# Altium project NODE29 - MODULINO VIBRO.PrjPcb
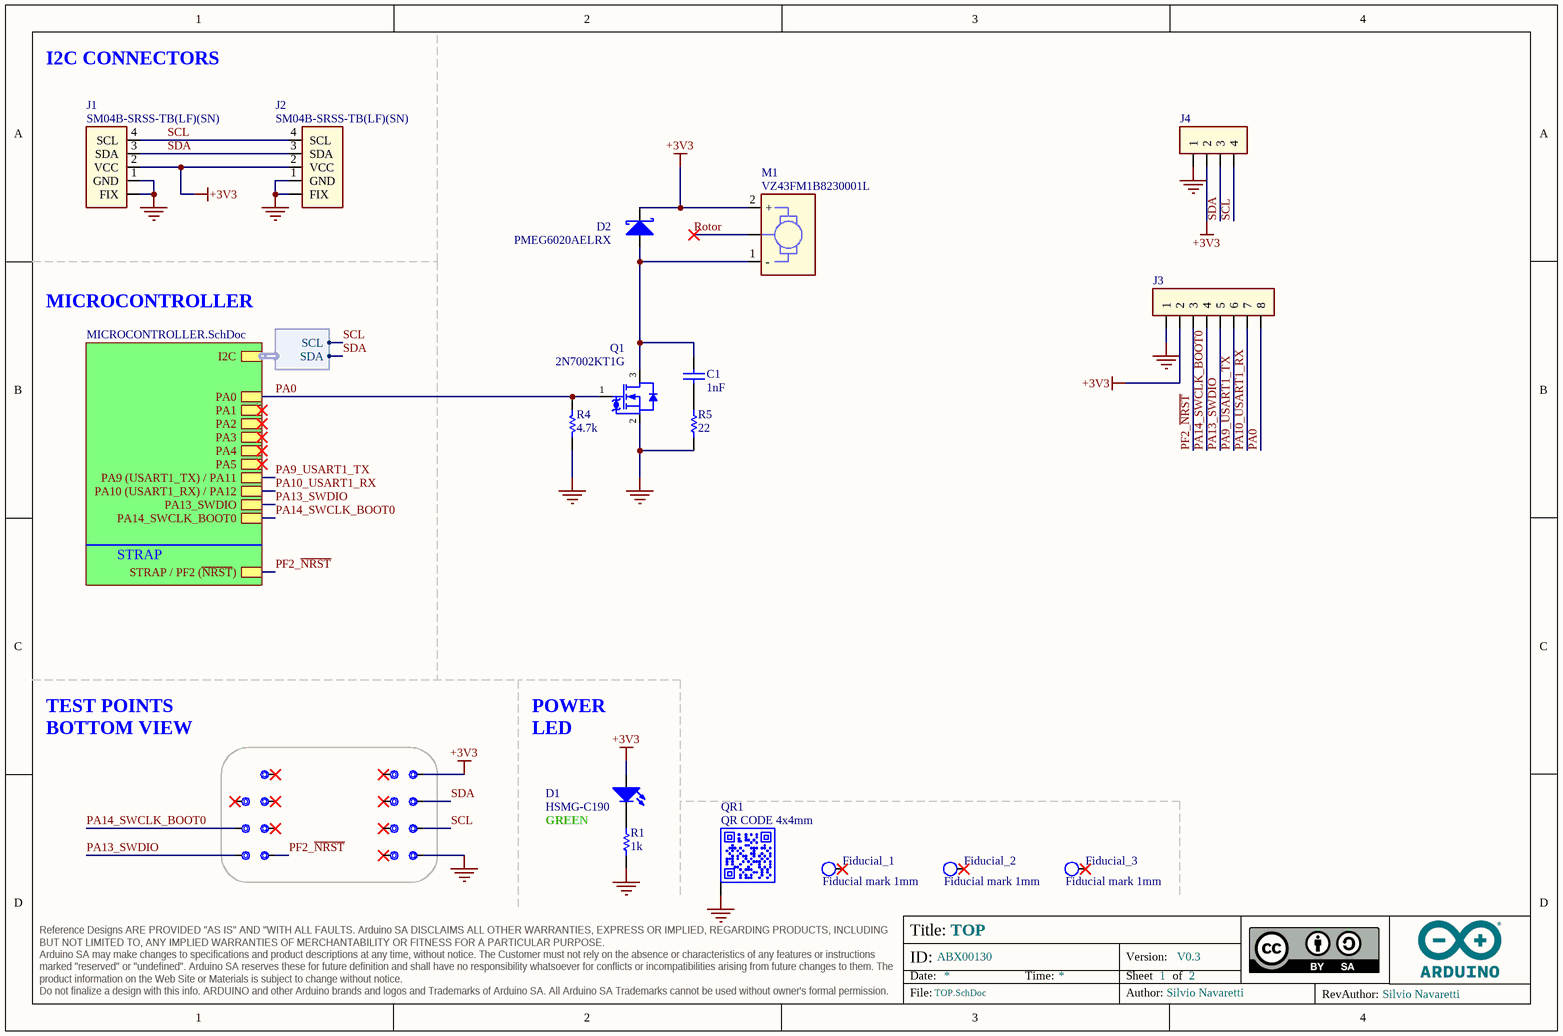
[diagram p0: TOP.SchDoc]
ASSEMBLY_BGA: _; ASSEMBLY_PRESSFIT: _; ASSEMBLY_SMD: X; ASSEMBLY_THT: _; BOARD_CODENAME: NODE29 - MODULINO VIBRO; BOARD_INFO_AUTHOR: Silvio Navaretti; BOARD_INFO_AUTHOR_REV: Silvio Navaretti; BOARD_INFO_Er: _; BOARD_INFO_FLEX: _; BOARD_INFO_FR4: X; BOARD_INFO_FR4_HTG: _; BOARD_INFO_IPC1: _; BOARD_INFO_IPC2: X; BOARD_INFO_IPC3: _; BOARD_INFO_IPC_NA: _; BOARD_INFO_NUMBER_OF_LAYERS: 2; BOARD_INFO_PCB_SIZE: 41.00x25.36mm; BOARD_INFO_POLYMIDE: _; BOARD_INFO_RIGID: X; BOARD_INFO_RIGID/FLEX: _; BOARD_INFO_TBD: _; BOARD_INFO_THICKNESS: 1.6mm; DRILLS_BLIND: _; DRILLS_BURIED: _; DRILLS_COPPER_FILLING: _; DRILLS_FULL: X; DRILLS_LASER: _; DRILLS_PRESSFIT: _; DRILLS_RESIN_FILLING: _; DRILLS_SLOT: _; DRILLS_SOLDER_FILLING: X; FINISH_ADJUSTMENTS: _; FINISH_EDGE_PLATING: _; FINISH_ENIG: _; FINISH_HAL: _; FINISH_HAL_LF: X; FINISH_NI/AU: _; FINISH_SILK_BOTTOM: X; FINISH_SILK_COLOR: WHITE; FINISH_SILK_TOP: X; FINISH_SN/PB: _; FINISH_SOLDERMASK_BOTTOM: X; FINISH_SOLDERMASK_COLOR: BLUE; FINISH_SOLDERMASK_PEELABLE_BOTTOM: _; FINISH_SOLDERMASK_PEELABLE_COLOR: _; FINISH_SOLDERMASK_PEELABLE_TOP: _; FINISH_SOLDERMASK_TOP: X; FINISH_TABS: _; FINISH_TBD: _; INSULATION_MIN_INNER: 0.15mm; INSULATION_MIN_OUTER: 0.15mm; PANEL_MILLING: X; PANEL_NOT_REQUESTED: _; PANEL_NUMBER_OF_FIGURES: 30; PANEL_PROVIDED: X; PANEL_REQUESTED: _; PANEL_SCORING: X; PANEL_SIZE: 262.00x221.00mm; PANEL_TABS: _; SKU: ABX00130; TRACK_MIN_WIDTH_INNER: 0.15mm; TRACK_MIN_WIDTH_OUTER: 0.15mm; Version: V0.3; VIA_1: _; VIA_1_HOLE_MM: _; VIA_1_PAD_MM: _; VIA_2: _; VIA_2_HOLE_MM: _; VIA_2_PAD_MM: _; VIA_3: _; VIA_3_HOLE_MM: _; VIA_3_PAD_MM: _; VIA_4: _; VIA_4_HOLE_MM: _; VIA_4_PAD_MM: _; VIA_5: _; VIA_5_HOLE_MM: _; VIA_5_PAD_MM: _; VIA_THROUGH: X; VIA_THROUGH_HOLE_MM: 0.3; VIA_THROUGH_PAD_MM: 0.6
2 sheets, 42 parts. Net scope: hierarchical (ports join the sheet entries above them; power ports are global).
Board files: PCB.PcbDoc, PANEL.PcbDoc
Sheets:
  TOP.SchDoc
    U_MICROCONTROLLER = MICROCONTROLLER.SchDoc

## Sheet TOP.SchDoc: TOP
size A4; Revision: V0.3; SheetNumber: 1; SheetTotal: 2

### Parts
3V3  Test point 1.00mm  [TP-1.00MM]  (value not drawn)  (no BOM)
C1  value 1nF  [CAP-0402]  (hidden comment: GRM155R71H102KA01D)
D1  HSMG-C190  [LEDC1608X80N-AK]
D2  PMEG6020AELRX  [SOD123-1]
Fiducial_1  Fiducial mark 1mm  [Fiducial mark 1mm-Footprint-1]  (no BOM)
Fiducial_2  Fiducial mark 1mm  [Fiducial mark 1mm-Footprint-1]  (no BOM)
Fiducial_3  Fiducial mark 1mm  [Fiducial mark 1mm-Footprint-1]  (no BOM)
GND  Test point 1.00mm  [TP-1.00MM]  (value not drawn)  (no BOM)
J1  SM04B-SRSS-TB(LF)(SN)  [SM04B-SRSS-TB(LF)(SN)-Footprint-1]
J2  SM04B-SRSS-TB(LF)(SN)  [SM04B-SRSS-TB(LF)(SN)-Footprint-1]
J3  HEADER TH 2.54mm VERT. 1x008POS  [PIN HEADER 2.54mm VERT. 1x8POS]  (value not drawn)  (no BOM)
J4  HEADER TH 2.54mm VERT. 1x004POS  [PIN HEADER 2.54mm VERT. 1x4POS-Footprint-1]  (value not drawn)  (no BOM)
M1  VZ43FM1B8230001L  [VZ43FM1B8230001L]
NRST  Test point 1.00mm  [TP-1.00MM]  (value not drawn)  (no BOM)
PA6  Test point 1.00mm  [TP-1.00MM]  (value not drawn)  (no BOM)
PA7  Test point 1.00mm  [TP-1.00MM]  (value not drawn)  (no BOM)
PC14  Test point 1.00mm  [TP-1.00MM]  (value not drawn)  (no BOM)
PC15  Test point 1.00mm  [TP-1.00MM]  (value not drawn)  (no BOM)
Q1  2N7002KT1G  [SOT23]
QR1  QR CODE 4x4mm  [QR CODE 4x4mm]  (no BOM)
R1  value 1k  [RES-0402]  (hidden comment: CRCW04021K00FKEDC)
R4  value 4.7k  [RES-0402]  (hidden comment: RC0402FR-074K7L)
R5  value 22  [RES-0603]  (hidden comment: CRCW060322R0FKEAC)
SCL  Test point 1.00mm  [TP-1.00MM]  (value not drawn)  (no BOM)
SDA  Test point 1.00mm  [TP-1.00MM]  (value not drawn)  (no BOM)
SWCLK  Test point 1.00mm  [TP-1.00MM]  (value not drawn)  (no BOM)
SWDIO  Test point 1.00mm  [TP-1.00MM]  (value not drawn)  (no BOM)
TP9  Test point 1.00mm  [TP-1.00MM]  (value not drawn)  (no BOM)
TP10  Test point 1.00mm  [TP-1.00MM]  (value not drawn)  (no BOM)
TP11  Test point 1.00mm  [TP-1.00MM]  (value not drawn)  (no BOM)
TP12  Test point 1.00mm  [TP-1.00MM]  (value not drawn)  (no BOM)

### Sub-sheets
U_MICROCONTROLLER = MICROCONTROLLER.SchDoc: I2C (harness I2C), PA0, PA1, PA2, PA3, PA4, PA5, PA13_SWDIO, PA14_SWCLK_BOOT0, PA9 (USART1_TX) / PA11, PA10 (USART1_RX) / PA12, STRAP / PF2 (~{NRST})

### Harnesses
I2C: SDA, SCL

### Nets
+3V3: 3V3.X D1.A D2.C J1.2(VCC) J2.2(VCC) J3.2 J4.2 M1.2(+)
GND: GND.X J1.1(GND) J1.FIX J2.1(GND) J2.FIX J3.1 J4.1 Q1.2(S) QR1.PAD R1.1 R4.2 R5.2
PA0: J3.8 Q1.1(G) R4.1 ; sheet U_MICROCONTROLLER/PA0
PA9_USART1_TX: J3.6 ; sheet U_MICROCONTROLLER/PA9 (USART1_TX) / PA11
PA10_USART1_RX: J3.7 ; sheet U_MICROCONTROLLER/PA10 (USART1_RX) / PA12
PA13_SWDIO: J3.5 SWCLK.X ; sheet U_MICROCONTROLLER/PA13_SWDIO
PA14_SWCLK_BOOT0: J3.4 SWDIO.X ; sheet U_MICROCONTROLLER/PA14_SWCLK_BOOT0
PF2_~{NRST}: J3.3 NRST.X ; sheet U_MICROCONTROLLER/STRAP / PF2 (~{NRST})
Rotor: M1.3  [project net Rotor_1]
SCL: J1.4(SCL) J2.4(SCL) J4.4 SCL.X ; sheet U_MICROCONTROLLER/I2C.SCL
SDA: J1.3(SDA) J2.3(SDA) J4.3 SDA.X ; sheet U_MICROCONTROLLER/I2C.SDA
NetC1_1: C1.1 R5.1
NetC1_2: C1.2 D2.A M1.1(-) Q1.3(D)
NetD1_C: D1.C R1.2

Not connected (* = marked no-connect by the designer): Fiducial_1 1*; Fiducial_2 1*; Fiducial_3 1*; PA6 X*; PA7 X*; PC14 X*; PC15 X*; TP9 X*; TP10 X*; TP11 X*; TP12 X*

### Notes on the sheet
- I2C CONNECTORS
- MICROCONTROLLER
- STRAP
- TEST POINTS BOTTOM VIEW
- (near D1) POWER LED
- GREEN

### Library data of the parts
3V3 GND NRST PA6 PA7 PC14 PC15 SCL SDA SWCLK SWDIO TP9-TP12 = UT0013-A.6: Manufacturer: This is not a component
C1 = C0007-A.15: CAP CHIP 0402 1nF 10% 50V X7R; Manufacturer: KEMET; Code Arduino: 2321
D1 = L0009-A.5: LED SMD 0603 GREEN/568 15mcd 120^; Manufacturer: Broadcom; Code Arduino: 2204
D2 = D0026-A.6: DIODE SCHOTTKY SMD 2A 60V SOD123FL; Manufacturer: Nexperia; Manucturer Part Number 2: SS26L; Code Arduino: 2208; Forward Voltage: 0.6V; Manucturer 2: Hottech
Fiducial_1-Fiducial_3 = UT0023-A.7: Fiducial mark 1mm clearance 2mm
J1 J2 = J0005-A.2: CONN JST 4POS SIDE 1MM TIN QWIIC; Code Arduino: J0005
J3 = J0171-A.4: Code Arduino: J0171
J4 = J0162-A.6: Code Arduino: J0162
M1 = S0061-A.3: MOTOR vibrator, 2.3V to 3.2V, max 75mA, 14000 RPM, DO NOT WASH, heigth 3.4mm, overall length 11mm; Manufacturer: Vybronics Inc; Code Arduino: S0061
Q1 = T0004-A.10: MOSFET N-CH 60V 300mA ESD prot. SOT23; Manufacturer: On Semiconductor; Device Type: Mosfet N-CH SMD; Code Arduino: A5393
QR1 = QR-0001-A.5: QR CODE 4x4mm on layer 34 (This is not a component); Code Arduino: QRCODE_4x4mm
R1 = R0007-A.24: RES CHIP 0402 1k 1% 1/16W; Manufacturer: Vishay; Code Arduino: 0140; Power: 62.5mW; Temperature coefficient: 100ppm
R4 = R0013-A.24: RES CHIP 0402 4k7 1% 1/16W; Manufacturer: YAGEO; Power: 62.5mW; Code Arduino: 2196; Temperature coefficient: 200ppm
R5 = R0121-A.22: RES CHIP 0603 22R 1% 1/10W; Manufacturer: Vishay; Code Arduino: A5106; Temperature coefficient: 100ppm; Power: 100mW

## Sheet MICROCONTROLLER.SchDoc: MICROCONTROLLER
size A4; SheetNumber: 2; SheetTotal: 2
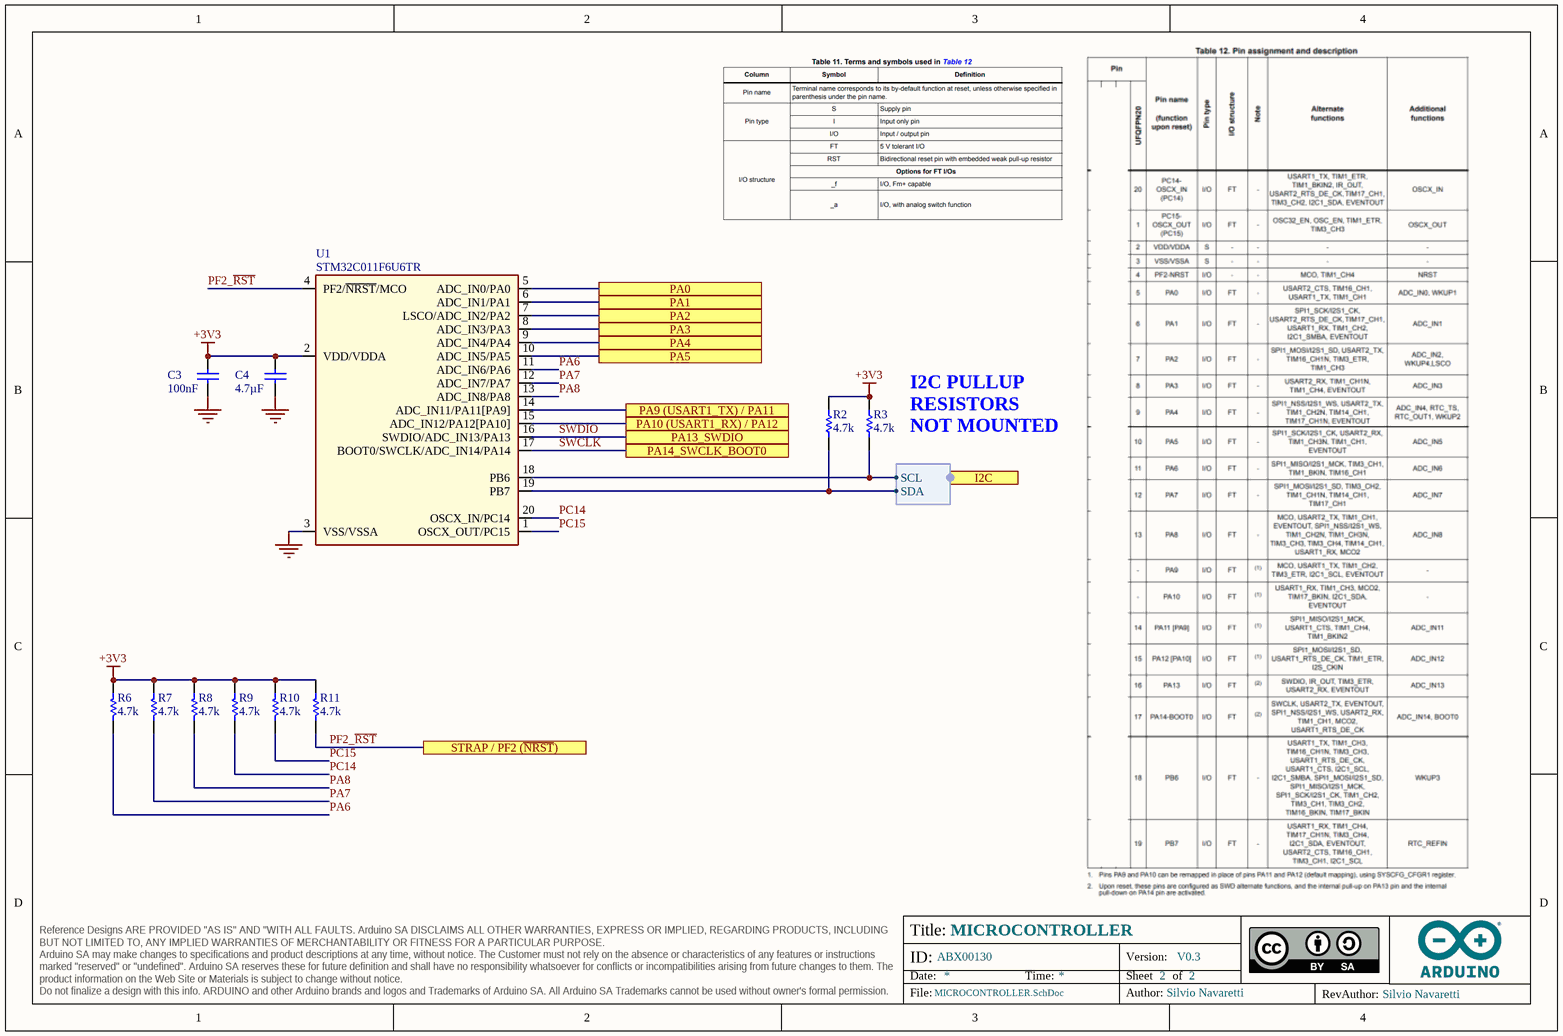
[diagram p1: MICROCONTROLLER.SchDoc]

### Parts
C3  value 100nF  [CAP-0402]  (hidden comment: 0402B104K160CT)
C4  value 4.7µF  [CAP-0603]  (hidden comment: GRM188R61C475KAAJD)
R2  value 4.7k  [RES-0402]  (hidden comment: RC0402FR-074K7L)
R3  value 4.7k  [RES-0402]  (hidden comment: RC0402FR-074K7L)
R6  value 4.7k  [RES-0402]  (hidden comment: RC0402FR-074K7L)
R7  value 4.7k  [RES-0402]  (hidden comment: RC0402FR-074K7L)
R8  value 4.7k  [RES-0402]  (hidden comment: RC0402FR-074K7L)
R9  value 4.7k  [RES-0402]  (hidden comment: RC0402FR-074K7L)
R10  value 4.7k  [RES-0402]  (hidden comment: RC0402FR-074K7L)
R11  value 4.7k  [RES-0402]  (hidden comment: RC0402FR-074K7L)
U1  STM32C011F6U6TR  [UFQFPN20]

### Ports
I2C (harness I2C), PA0, PA1, PA2, PA3, PA4, PA5, PA9 (USART1_TX) / PA11, PA10 (USART1_RX) / PA12, PA13_SWDIO, PA14_SWCLK_BOOT0, STRAP / PF2 (~{NRST})

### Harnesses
I2C: SDA, SCL

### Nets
+3V3: C3.1 C4.2 R2.2 R3.2 R6.1 R7.1 R8.1 R9.1 R10.1 R11.1 U1.2(VDD/VDDA)
GND: C3.2 C4.1 U1.3(VSS/VSSA)
PA0: U1.5(ADC_IN0/PA0) ; port PA0
PA6: R6.2 U1.11(ADC_IN6/PA6)  [project net PA6_2]
PA7: R7.2 U1.12(ADC_IN7/PA7)  [project net PA7_2]
PA8: R8.2 U1.13(ADC_IN8/PA8)  [project net PA8_2]
PA9_USART1_TX: U1.14(ADC_IN11/PA11[PA9]) ; port PA9 (USART1_TX) / PA11
PA10_USART1_RX: U1.15(ADC_IN12/PA12[PA10]) ; port PA10 (USART1_RX) / PA12
PC14: R9.2 U1.20(OSCX_IN/PC14)  [project net PC14_2]
PC15: R10.2 U1.1(OSCX_OUT/PC15)  [project net PC15_2]
PF2_~{RST}: R11.2 U1.4(PF2/~{NRST}/MCO) ; port STRAP / PF2 (~{NRST})  [project net PF2_~{NRST}]
SCL: R3.1 U1.18(PB6) ; port I2C.SCL
SDA: R2.1 U1.19(PB7) ; port I2C.SDA
SWCLK: U1.17(BOOT0/SWCLK/ADC_IN14/PA14) ; port PA14_SWCLK_BOOT0  [project net PA14_SWCLK_BOOT0]
SWDIO: U1.16(SWDIO/ADC_IN13/PA13) ; port PA13_SWDIO  [project net PA13_SWDIO]
NetU1_6: U1.6(ADC_IN1/PA1) ; port PA1
NetU1_7: U1.7(LSCO/ADC_IN2/PA2) ; port PA2
NetU1_8: U1.8(ADC_IN3/PA3) ; port PA3
NetU1_9: U1.9(ADC_IN4/PA4) ; port PA4
NetU1_10: U1.10(ADC_IN5/PA5) ; port PA5

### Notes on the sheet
- (near R3) I2C PULLUP RESISTORS NOT MOUNTED

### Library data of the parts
C3 = C0012-A.15: CAP CHIP 0402 100nF 10% 16V X7R; Manufacturer: Walsin; Code Arduino: 0132
C4 = C0054-A.16: CAP CHIP 0603 4.7uF 10% 16V X5R; Manufacturer: Murata; Code Arduino: A5072
R2 R3 = R0013-A.24: RES CHIP 0402 4k7 1% 1/16W; Manufacturer: YAGEO; Code Arduino: 2196; Power: 62.5mW; Temperature coefficient: 200ppm
R6-R11 = R0013-A.24: as R4 on sheet TOP
U1 = U0390-A.1: IC Cortex M0, 32b MCU, 32KB Flash, 6KB RAM, VDD 2-3.6V, -40°C to 85°C, QFN20 3x3mm; Manufacturer: ST Microelectronics; Code Arduino: U0390

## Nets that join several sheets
+3V3: TOP (8 pins), MICROCONTROLLER (11 pins)
GND: TOP (12 pins), MICROCONTROLLER (C3.2 C4.1 U1.3)
PA0: TOP (J3.8 Q1.1 R4.1), MICROCONTROLLER (U1.5)
PA9_USART1_TX: TOP (J3.6), MICROCONTROLLER (U1.14)
PA10_USART1_RX: TOP (J3.7), MICROCONTROLLER (U1.15)
PA13_SWDIO: TOP (J3.5 SWCLK.X), MICROCONTROLLER (U1.16)
PA14_SWCLK_BOOT0: TOP (J3.4 SWDIO.X), MICROCONTROLLER (U1.17)
PF2_~{NRST}: TOP (J3.3 NRST.X), MICROCONTROLLER (R11.2 U1.4)
SCL: TOP (J1.4 J2.4 J4.4 SCL.X), MICROCONTROLLER (R3.1 U1.18)
SDA: TOP (J1.3 J2.3 J4.3 SDA.X), MICROCONTROLLER (R2.1 U1.19)

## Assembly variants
ABX00130: not fitted R2 R3 R9 R10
